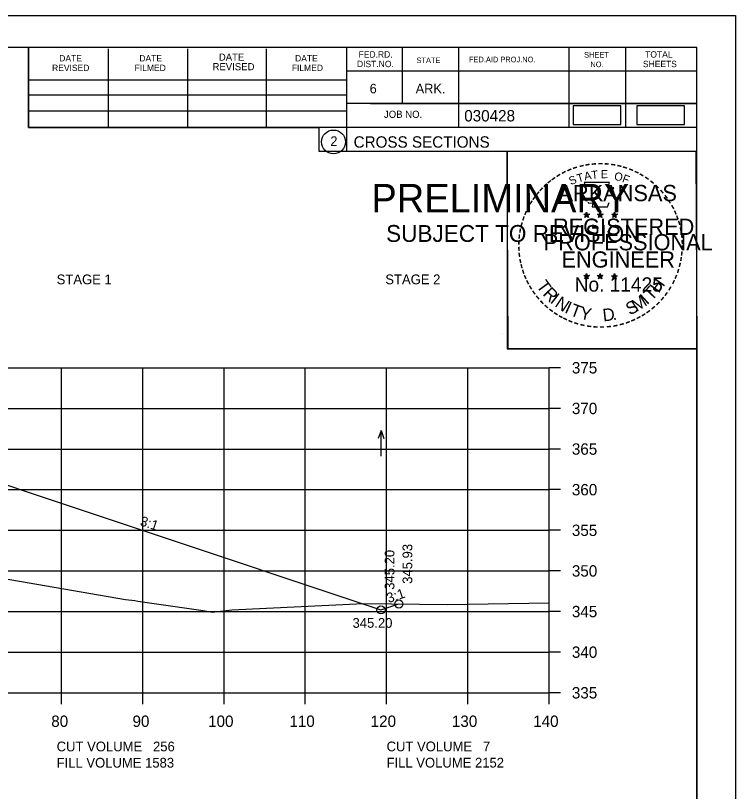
# Model space of a CAD drawing. Extents: x 1374859 to 1376773, y 382242 to 389804.
# Drawn here: x 1376684.8 to 1376773.4, y 383426.3 to 383521.8 of the extents above; entities that cross this region are included whole.
import ezdxf

# ---------------------------------------------------------------- set-up
doc = ezdxf.new("R2010")
doc.units = 0
for name, color, linetype in [('R_Axis', 7, 'Continuous'), ('R_Axis Annot', 7, 'Continuous'), ('R_Border', 7, 'Continuous'), ('R_Border PE', 7, 'Continuous'), ('R_Border Prem', 7, 'Continuous'), ('R_Exist Surface', 7, 'Continuous'), ('R_Fin Surface', 7, 'Continuous'), ('R_Grid', 7, 'Continuous'), ('R_MOT', 7, 'Continuous'), ('R_No Plot', 7, 'Continuous'), ('R_Water Annot', 7, 'Continuous'), ('R_Xsect Elev', 7, 'Continuous'), ('R_Xsect Slope', 7, 'Continuous')]:
    doc.layers.add(name, color=color, linetype=linetype)

msp = doc.modelspace()

# ---------------------------------------------------------------- linework, layer by layer
at = {"layer": 'R_Axis'}
for p, q in [((1376750.452, 383438.41), (1376750.452, 383478.41)), ((1376751.852, 383478.41), (1376750.452, 383478.41)), ((1376751.852, 383473.41), (1376750.452, 383473.41)), ((1376751.852, 383468.41), (1376750.452, 383468.41)), ((1376751.852, 383463.41), (1376750.452, 383463.41)), ((1376751.852, 383458.41), (1376750.452, 383458.41)), ((1376751.852, 383453.41), (1376750.452, 383453.41)), ((1376751.852, 383448.41), (1376750.452, 383448.41)), ((1376751.852, 383443.41), (1376750.452, 383443.41)), ((1376470.452, 383438.41), (1376750.452, 383438.41)), ((1376690.452, 383437.01), (1376690.452, 383438.41)), ((1376700.452, 383437.01), (1376700.452, 383438.41)), ((1376710.452, 383437.01), (1376710.452, 383438.41)), ((1376720.452, 383437.01), (1376720.452, 383438.41)), ((1376730.452, 383437.01), (1376730.452, 383438.41)), ((1376740.452, 383437.01), (1376740.452, 383438.41)), ((1376750.452, 383437.01), (1376750.452, 383438.41)), ((1376751.852, 383438.41), (1376750.452, 383438.41))]:
    msp.add_line(p, q, dxfattribs=at)
at = {"layer": 'R_Border'}
for p, q in [((1376452.452, 383517.87), (1376768.632, 383517.87)), ((1376686.372, 383507.99), (1376686.372, 383517.87)), ((1376696.232, 383507.99), (1376696.232, 383517.67)), ((1376705.992, 383507.99), (1376705.992, 383517.67)), ((1376715.672, 383507.99), (1376715.672, 383517.67)), ((1376725.532, 383517.87), (1376725.532, 383505.07)), ((1376732.372, 383517.87), (1376732.372, 383510.93)), ((1376739.312, 383517.87), (1376739.312, 383507.99)), ((1376752.892, 383517.87), (1376752.892, 383507.99)), ((1376759.832, 383517.87), (1376759.832, 383507.99)), ((1376768.632, 383312.41), (1376768.632, 383517.87)), ((1376768.632, 383514.93), (1376725.532, 383514.93)), ((1376768.632, 383514.95), (1376768.632, 383514.95)), ((1376686.372, 383513.85), (1376725.532, 383513.85)), ((1376686.372, 383511.99), (1376725.532, 383511.99)), ((1376768.632, 383510.93), (1376725.532, 383510.93)), ((1376728.492, 383510.93), (1376768.632, 383510.93)), ((1376686.372, 383507.99), (1376686.372, 383510.05)), ((1376686.372, 383510.05), (1376725.532, 383510.05)), ((1376768.632, 383507.99), (1376686.372, 383507.99)), ((1376725.532, 383505.07), (1376768.632, 383505.07))]:
    msp.add_line(p, q, dxfattribs=at)
msp.add_circle((1376723.918, 383506.206), 1.467, dxfattribs=at)
at = {"layer": 'R_Border PE'}
for p, q in [((1376754.717, 383497.325), (1376755.066, 383497.214)), ((1376754.717, 383497.325), (1376754.97, 383497.28)), ((1376754.717, 383497.325), (1376754.954, 383497.203)), ((1376754.85, 383496.917), (1376755.066, 383497.214)), ((1376755.066, 383497.579), (1376755.025, 383497.327)), ((1376755.066, 383497.214), (1376755.066, 383497.579)), ((1376755.066, 383497.579), (1376755.115, 383497.329)), ((1376755.413, 383497.325), (1376755.066, 383497.214)), ((1376755.279, 383496.917), (1376755.066, 383497.214)), ((1376755.413, 383497.325), (1376755.127, 383497.276)), ((1376755.279, 383496.917), (1376755.142, 383497.208)), ((1376755.413, 383497.325), (1376755.209, 383497.223)), ((1376756.387, 383497.325), (1376756.736, 383497.214)), ((1376756.387, 383497.325), (1376756.64, 383497.28)), ((1376756.387, 383497.325), (1376756.624, 383497.203)), ((1376756.52, 383496.917), (1376756.736, 383497.214)), ((1376756.736, 383497.579), (1376756.695, 383497.327)), ((1376756.736, 383497.214), (1376756.736, 383497.579)), ((1376756.736, 383497.579), (1376756.785, 383497.329)), ((1376757.083, 383497.325), (1376756.736, 383497.214)), ((1376756.949, 383496.917), (1376756.736, 383497.214)), ((1376757.083, 383497.325), (1376756.797, 383497.276)), ((1376756.949, 383496.917), (1376756.812, 383497.208)), ((1376757.083, 383497.325), (1376756.879, 383497.223)), ((1376758.151, 383497.313), (1376758.5, 383497.202)), ((1376758.151, 383497.313), (1376758.404, 383497.268)), ((1376758.151, 383497.313), (1376758.388, 383497.191)), ((1376758.5, 383497.567), (1376758.459, 383497.315)), ((1376758.5, 383497.202), (1376758.5, 383497.567)), ((1376758.5, 383497.567), (1376758.549, 383497.317)), ((1376758.847, 383497.313), (1376758.5, 383497.202)), ((1376758.847, 383497.313), (1376758.561, 383497.264)), ((1376758.847, 383497.313), (1376758.643, 383497.211)), ((1376754.85, 383496.917), (1376754.976, 383497.161)), ((1376754.85, 383496.917), (1376755.064, 383497.134)), ((1376755.279, 383496.917), (1376755.064, 383497.131)), ((1376756.52, 383496.917), (1376756.646, 383497.161)), ((1376756.52, 383496.917), (1376756.734, 383497.134)), ((1376756.949, 383496.917), (1376756.734, 383497.131)), ((1376758.284, 383496.905), (1376758.5, 383497.202)), ((1376758.284, 383496.905), (1376758.41, 383497.149)), ((1376758.284, 383496.905), (1376758.498, 383497.122)), ((1376758.713, 383496.905), (1376758.498, 383497.119)), ((1376758.713, 383496.905), (1376758.5, 383497.202)), ((1376758.713, 383496.905), (1376758.576, 383497.196)), ((1376754.713, 383489.752), (1376755.062, 383489.641)), ((1376754.713, 383489.752), (1376754.966, 383489.707)), ((1376754.713, 383489.752), (1376754.95, 383489.63)), ((1376754.846, 383489.344), (1376755.062, 383489.641)), ((1376754.846, 383489.344), (1376754.972, 383489.588)), ((1376755.062, 383490.006), (1376755.021, 383489.754)), ((1376755.062, 383489.641), (1376755.062, 383490.006)), ((1376755.062, 383490.006), (1376755.111, 383489.756)), ((1376755.409, 383489.752), (1376755.062, 383489.641)), ((1376755.275, 383489.344), (1376755.062, 383489.641)), ((1376755.409, 383489.752), (1376755.123, 383489.703)), ((1376755.275, 383489.344), (1376755.138, 383489.635)), ((1376755.409, 383489.752), (1376755.205, 383489.65)), ((1376756.382, 383489.752), (1376756.731, 383489.641)), ((1376756.382, 383489.752), (1376756.635, 383489.707)), ((1376756.382, 383489.752), (1376756.619, 383489.63)), ((1376756.515, 383489.344), (1376756.731, 383489.641)), ((1376756.515, 383489.344), (1376756.641, 383489.588)), ((1376756.731, 383490.006), (1376756.69, 383489.754)), ((1376756.731, 383489.641), (1376756.731, 383490.006)), ((1376756.731, 383490.006), (1376756.78, 383489.756)), ((1376757.078, 383489.752), (1376756.731, 383489.641)), ((1376756.944, 383489.344), (1376756.731, 383489.641)), ((1376757.078, 383489.752), (1376756.792, 383489.703)), ((1376756.944, 383489.344), (1376756.807, 383489.635)), ((1376757.078, 383489.752), (1376756.874, 383489.65)), ((1376758.149, 383489.742), (1376758.498, 383489.631)), ((1376758.149, 383489.742), (1376758.402, 383489.697)), ((1376758.149, 383489.742), (1376758.386, 383489.62)), ((1376758.282, 383489.334), (1376758.498, 383489.631)), ((1376758.282, 383489.334), (1376758.408, 383489.578)), ((1376758.498, 383489.996), (1376758.457, 383489.744)), ((1376758.498, 383489.631), (1376758.498, 383489.996)), ((1376758.498, 383489.996), (1376758.547, 383489.746)), ((1376758.845, 383489.742), (1376758.498, 383489.631)), ((1376758.711, 383489.334), (1376758.498, 383489.631)), ((1376758.845, 383489.742), (1376758.559, 383489.693)), ((1376758.711, 383489.334), (1376758.574, 383489.625)), ((1376758.845, 383489.742), (1376758.641, 383489.64)), ((1376754.846, 383489.344), (1376755.06, 383489.561)), ((1376755.275, 383489.344), (1376755.06, 383489.558)), ((1376756.515, 383489.344), (1376756.729, 383489.561)), ((1376756.944, 383489.344), (1376756.729, 383489.558)), ((1376758.282, 383489.334), (1376758.496, 383489.551)), ((1376758.711, 383489.334), (1376758.496, 383489.548))]:
    msp.add_line(p, q, dxfattribs=at)
for points in [[(1376754.758, 383501.203), (1376755.027, 383500.376)], [(1376758.269, 383500.281), (1376758.411, 383500.565), (1376757.726, 383500.541), (1376757.874, 383501.203), (1376754.758, 383501.203)], [(1376755.25, 383498.78), (1376755.25, 383498.693), (1376755.813, 383498.674), (1376755.759, 383498.201), (1376757.629, 383498.201), (1376757.83, 383498.737)], [(1376755.066, 383497.579), (1376755.279, 383496.917), (1376754.717, 383497.325), (1376755.413, 383497.325), (1376754.85, 383496.917), (1376755.066, 383497.579)], [(1376756.736, 383497.579), (1376756.949, 383496.917), (1376756.387, 383497.325), (1376757.083, 383497.325), (1376756.52, 383496.917), (1376756.736, 383497.579)], [(1376758.5, 383497.567), (1376758.713, 383496.905), (1376758.151, 383497.313), (1376758.847, 383497.313), (1376758.284, 383496.905), (1376758.5, 383497.567)], [(1376755.062, 383490.006), (1376755.275, 383489.344), (1376754.713, 383489.752), (1376755.409, 383489.752), (1376754.846, 383489.344), (1376755.062, 383490.006)], [(1376756.731, 383490.006), (1376756.944, 383489.344), (1376756.382, 383489.752), (1376757.078, 383489.752), (1376756.515, 383489.344), (1376756.731, 383490.006)], [(1376758.498, 383489.996), (1376758.711, 383489.334), (1376758.149, 383489.742), (1376758.845, 383489.742), (1376758.282, 383489.334), (1376758.498, 383489.996)]]:
    msp.add_lwpolyline(points, dxfattribs=at)
for centre, radius in [((1376755.065, 383497.213), 0.172), ((1376755.065, 383497.213), 0.145), ((1376755.065, 383497.213), 0.116), ((1376755.065, 383497.213), 0.0991), ((1376755.065, 383497.213), 0.0747), ((1376755.065, 383497.213), 0.0495), ((1376755.065, 383497.213), 0.0296), ((1376756.735, 383497.213), 0.172), ((1376756.735, 383497.213), 0.145), ((1376756.735, 383497.213), 0.116), ((1376756.735, 383497.213), 0.0991), ((1376756.735, 383497.213), 0.0747), ((1376756.735, 383497.213), 0.0495), ((1376756.735, 383497.213), 0.0296), ((1376758.499, 383497.201), 0.172), ((1376758.499, 383497.201), 0.145), ((1376758.499, 383497.201), 0.116), ((1376758.499, 383497.201), 0.0991), ((1376758.499, 383497.201), 0.0747), ((1376758.499, 383497.201), 0.0495), ((1376758.499, 383497.201), 0.0296), ((1376755.061, 383489.64), 0.172), ((1376755.061, 383489.64), 0.145), ((1376755.061, 383489.64), 0.116), ((1376755.061, 383489.64), 0.0991), ((1376755.061, 383489.64), 0.0747), ((1376755.061, 383489.64), 0.0495), ((1376755.061, 383489.64), 0.0296), ((1376756.73, 383489.64), 0.172), ((1376756.73, 383489.64), 0.145), ((1376756.73, 383489.64), 0.116), ((1376756.73, 383489.64), 0.0991), ((1376756.73, 383489.64), 0.0747), ((1376756.73, 383489.64), 0.0495), ((1376756.73, 383489.64), 0.0296), ((1376758.497, 383489.63), 0.172), ((1376758.497, 383489.63), 0.145), ((1376758.497, 383489.63), 0.116), ((1376758.497, 383489.63), 0.0991), ((1376758.497, 383489.63), 0.0747), ((1376758.497, 383489.63), 0.0495), ((1376758.497, 383489.63), 0.0296)]:
    msp.add_circle(centre, radius, dxfattribs=at)
at = {"layer": 'R_Exist Surface'}
msp.add_lwpolyline([(1376668.854, 383456.298), (1376674.332, 383454.055), (1376698.323, 383449.876), (1376699.464, 383449.757), (1376699.852, 383449.673), (1376707.879, 383448.53), (1376708.984, 383448.348), (1376711.42, 383448.606), (1376727.625, 383449.38), (1376737.959, 383449.29), (1376750.452, 383449.464)], dxfattribs=at)
at = {"layer": 'R_Fin Surface'}
msp.add_lwpolyline([(1376485.181, 383452.493), (1376502.811, 383446.616), (1376550.967, 383462.668), (1376558.854, 383463.983), (1376571.044, 383466.015), (1376580.967, 383466.65), (1376610.467, 383468.539), (1376639.967, 383470.428), (1376653.467, 383471.292), (1376669.721, 383468.583), (1376669.967, 383468.542), (1376729.762, 383448.61), (1376731.96, 383449.343)], dxfattribs=at)
at = {"layer": 'R_Grid'}
for p, q in [((1376470.452, 383478.41), (1376750.452, 383478.41)), ((1376470.452, 383478.41), (1376750.452, 383478.41)), ((1376690.452, 383438.41), (1376690.452, 383478.41)), ((1376690.452, 383438.41), (1376690.452, 383478.41)), ((1376700.452, 383438.41), (1376700.452, 383478.41)), ((1376700.452, 383438.41), (1376700.452, 383478.41)), ((1376710.452, 383438.41), (1376710.452, 383478.41)), ((1376710.452, 383438.41), (1376710.452, 383478.41)), ((1376720.452, 383438.41), (1376720.452, 383478.41)), ((1376720.452, 383438.41), (1376720.452, 383478.41)), ((1376730.452, 383438.41), (1376730.452, 383478.41)), ((1376730.452, 383438.41), (1376730.452, 383478.41)), ((1376740.452, 383438.41), (1376740.452, 383478.41)), ((1376740.452, 383438.41), (1376740.452, 383478.41)), ((1376750.452, 383438.41), (1376750.452, 383478.41)), ((1376750.452, 383438.41), (1376750.452, 383478.41)), ((1376470.452, 383473.41), (1376750.452, 383473.41)), ((1376470.452, 383473.41), (1376750.452, 383473.41)), ((1376470.452, 383468.41), (1376750.452, 383468.41)), ((1376470.452, 383468.41), (1376750.452, 383468.41)), ((1376470.452, 383463.41), (1376750.452, 383463.41)), ((1376470.452, 383463.41), (1376750.452, 383463.41)), ((1376470.452, 383458.41), (1376750.452, 383458.41)), ((1376470.452, 383458.41), (1376750.452, 383458.41)), ((1376470.452, 383453.41), (1376750.452, 383453.41)), ((1376470.452, 383453.41), (1376750.452, 383453.41)), ((1376470.452, 383448.41), (1376750.452, 383448.41)), ((1376470.452, 383448.41), (1376750.452, 383448.41)), ((1376470.452, 383443.41), (1376750.452, 383443.41)), ((1376470.452, 383443.41), (1376750.452, 383443.41)), ((1376470.452, 383438.41), (1376750.452, 383438.41)), ((1376470.452, 383438.41), (1376750.452, 383438.41))]:
    msp.add_line(p, q, dxfattribs=at)
at = {"layer": 'R_MOT'}
for points in [[(1376753.43, 383508.334), (1376759.263, 383508.334), (1376759.263, 383510.644), (1376753.43, 383510.644)], [(1376761.261, 383508.334), (1376767.094, 383508.334), (1376767.094, 383510.644), (1376761.261, 383510.644)]]:
    msp.add_lwpolyline(points, close=True, dxfattribs=at)
at = {"layer": 'R_No Plot'}
for p, q in [((1376440.051, 383521.765), (1376773.384, 383521.765)), ((1376744.666, 383482.615), (1376744.666, 383482.615))]:
    msp.add_line(p, q, dxfattribs=at)
for points in [[(1376440.044, 383521.765), (1376773.384, 383521.765), (1376773.384, 383308.427), (1376440.044, 383308.427)], [(1376686.372, 383517.87), (1376686.372, 383507.99), (1376722.104, 383507.99), (1376722.104, 383505.07), (1376745.303, 383505.07), (1376745.303, 383480.737), (1376768.632, 383480.737), (1376768.632, 383312.41), (1376452.452, 383312.41), (1376452.452, 383517.87)], [(1376745.303, 383505.07), (1376768.511, 383505.07), (1376768.632, 383480.737), (1376745.424, 383480.737)]]:
    msp.add_lwpolyline(points, close=True, dxfattribs=at)
for centre in [(1376731.96, 383449.343), (1376729.762, 383448.61)]:
    msp.add_circle(centre, 0.5, dxfattribs=at)
at = {"layer": 'R_Water Annot'}
for p, q in [((1376729.773, 383470.681), (1376729.423, 383469.72)), ((1376729.773, 383467.539), (1376729.773, 383470.681)), ((1376729.773, 383470.681), (1376730.123, 383469.72))]:
    msp.add_line(p, q, dxfattribs=at)

# ---------------------------------------------------------------- texts
at = {"layer": 'R_Axis Annot'}
for s, p in [('STAGE 1', (1376689.855, 383488.69)), ('STAGE 2', (1376730.296, 383488.692))]:
    msp.add_text(s, height=1.2, rotation=360, dxfattribs=at).set_placement(p)
for s, height, p in [('375', 1.4, (1376753.252, 383477.71)), ('370', 1.4, (1376753.252, 383472.71)), ('365', 1.4, (1376753.252, 383467.71)), ('360', 1.4, (1376753.252, 383462.71)), ('355', 1.4, (1376753.252, 383457.71)), ('350', 1.4, (1376753.252, 383452.71)), ('345', 1.4, (1376753.252, 383447.71)), ('340', 1.4, (1376753.252, 383442.71)), ('335', 1.4, (1376753.252, 383437.71)), ('80', 1.4, (1376689.19, 383434.21)), ('90', 1.4, (1376699.19, 383434.21)), ('100', 1.4, (1376708.49, 383434.21)), ('110', 1.4, (1376718.49, 383434.21)), ('120', 1.4, (1376728.49, 383434.21)), ('130', 1.4, (1376738.49, 383434.21)), ('140', 1.4, (1376748.49, 383434.21)), ('CUT VOLUME   256', 1.2, (1376689.855, 383431.203)), ('CUT VOLUME   7', 1.2, (1376730.452, 383431.21)), ('FILL VOLUME 1583', 1.2, (1376689.855, 383429.203)), ('FILL VOLUME 2152', 1.2, (1376730.452, 383429.21))]:
    msp.add_text(s, height=height, dxfattribs=at).set_placement(p)
at = {"layer": 'R_Border'}
for s, height, p in [('FED.RD.', 0.7819, (1376727.012, 383516.59)), ('SHEET', 0.684, (1376754.752, 383516.59)), ('TOTAL', 0.7819, (1376762.272, 383516.59)), ('DATE', 0.7819, (1376690.172, 383516.11)), ('DATE', 0.7819, (1376700.032, 383516.11)), ('DATE', 0.8792, (1376709.812, 383516.21)), ('DATE', 0.7819, (1376719.192, 383516.11)), ('STATE', 0.684, (1376734.132, 383515.91)), ('FED.AID PROJ.NO.', 0.684, (1376740.592, 383516.01)), ('REVISED', 0.7819, (1376689.292, 383514.93)), ('FILMED', 0.7819, (1376699.452, 383514.93)), ('REVISED', 0.8792, (1376709.032, 383515.03)), ('FILMED', 0.7819, (1376718.792, 383514.93)), ('DIST.NO.', 0.7819, (1376726.812, 383515.41)), ('NO.', 0.684, (1376755.532, 383515.41)), ('SHEETS', 0.7819, (1376761.992, 383515.41)), ('6', 1.172, (1376728.372, 383512.19)), ('ARK.', 1.1723, (1376734.032, 383512.19)), ('JOB NO.', 0.8792, (1376730.132, 383509.17)), ('030428', 1.4, (1376740.008, 383508.73)), ('2', 1.172, (1376723.536, 383505.719)), ('CROSS SECTIONS', 1.4, (1376726.395, 383505.5))]:
    msp.add_text(s, height=height, rotation=360, dxfattribs=at).set_placement(p)
at = {"layer": 'R_Border PE'}
for s, height, rotation, p in [('-', 1.6, 24.30721, (1376752.871, 383502.061)), ('-', 1.6, 19.17608, (1376753.505, 383502.33)), ('-', 1.6, 13.63015, (1376754.255, 383502.571)), ('-', 1.6, 10.21935, (1376754.933, 383502.733)), ('-', 1.6, 5.89682, (1376755.662, 383502.843)), ('-', 1.6, 0.18623, (1376756.434, 383502.915)), ('-', 1.6, 357.74304, (1376757.157, 383502.902)), ('-', 1.6, 352.16172, (1376757.901, 383502.846)), ('-', 1.6, 347.20489, (1376758.62, 383502.732)), ('-', 1.6, 342.3362, (1376759.255, 383502.577)), ('-', 1.6, 337.85509, (1376759.99, 383502.354)), ('-', 1.6, 34.06357, (1376751.641, 383501.374)), ('-', 1.6, 28.79182, (1376752.238, 383501.744)), ('S', 1, 21.59401, (1376753.112, 383500.881)), ('T', 1, 16.4036, (1376754.026, 383501.212)), ('A', 1, 11.21318, (1376754.852, 383501.463)), ('T', 1, 6.02276, (1376755.701, 383501.629)), ('E', 1, 0.83234, (1376756.806, 383501.739)), ('O', 1, 350.4515, (1376758.41, 383501.529)), ('F', 1, 340.07066, (1376759.364, 383501.301)), ('-', 1.6, 334.12109, (1376760.621, 383502.083)), ('-', 1.6, 329.64089, (1376761.2, 383501.8)), ('-', 1.6, 42.96224, (1376750.154, 383500.184)), ('-', 1.6, 38.95066, (1376750.587, 383500.601)), ('-', 1.6, 36.23174, (1376751.063, 383500.979)), ('-', 1.6, 325.86266, (1376761.843, 383501.439)), ('-', 1.6, 320.52971, (1376762.453, 383501.013)), ('-', 1.6, 50.61417, (1376749.303, 383499.22)), ('-', 1.6, 48.42305, (1376749.706, 383499.706)), ('ARKANSAS', 2, 360, (1376751.61, 383498.915)), ('-', 1.6, 315.57859, (1376763.052, 383500.525)), ('-', 1.6, 309.87973, (1376763.621, 383499.975)), ('-', 1.6, 54.23247, (1376748.89, 383498.653)), ('-', 1.6, 306.65218, (1376764.146, 383499.373)), ('-', 1.6, 62.87135, (1376748.252, 383497.512)), ('-', 1.6, 58.07063, (1376748.565, 383498.126)), ('-', 1.4, 303.67529, (1376764.632, 383498.805)), ('-', 1.6, 299.66835, (1376764.951, 383498.198)), ('-', 1.6, 67.77427, (1376747.993, 383496.901)), ('DWB', 0.01, 360, (1376755.053, 383497.209)), ('DWB', 0.01, 360, (1376756.723, 383497.209)), ('DWB', 0.01, 360, (1376758.487, 383497.198)), ('-', 1.6, 294.66279, (1376765.275, 383497.586)), ('-', 1.6, 75.46096, (1376747.577, 383495.557)), ('-', 1.6, 72.39447, (1376747.774, 383496.271)), ('REGISTERED', 2, 360, (1376750.932, 383494.766)), ('-', 1.6, 290.57283, (1376765.532, 383497.009)), ('-', 1.6, 285.12326, (1376765.766, 383496.429)), ('-', 1.6, 81.20126, (1376747.445, 383494.844)), ('-', 1.6, 280.54934, (1376765.966, 383495.687)), ('-', 1.6, 85.18634, (1376747.369, 383494.153)), ('PROFESSIONAL', 2, 360, (1376749.784, 383492.862)), ('-', 1.6, 276.59616, (1376766.128, 383494.919)), ('-', 1.6, 89.06224, (1376747.344, 383493.452)), ('-', 1.6, 274.33011, (1376766.188, 383494.197)), ('-', 1.6, 269.94067, (1376766.222, 383493.565)), ('-', 1.6, 94.19588, (1376747.379, 383492.727)), ('-', 1.6, 98.94793, (1376747.451, 383492.06)), ('ENGINEER', 2, 360, (1376751.971, 383490.737)), ('-', 1.6, 263.5172, (1376766.203, 383492.899)), ('-', 1.6, 101.71495, (1376747.586, 383491.327)), ('-', 1.6, 260.99529, (1376766.132, 383492.245)), ('-', 1.6, 105.45785, (1376747.748, 383490.732)), ('-', 1.6, 252.86809, (1376765.841, 383490.847)), ('-', 1.6, 255.7626, (1376766.022, 383491.567)), ('-', 1.6, 109.08742, (1376747.963, 383490.101)), ('-', 1.6, 114.06432, (1376748.217, 383489.505)), ('No. 11425', 1.757, 360, (1376753.599, 383487.786)), ('DWB', 0.01, 360, (1376755.049, 383489.636)), ('DWB', 0.01, 360, (1376756.718, 383489.636)), ('DWB', 0.01, 360, (1376758.485, 383489.626)), ('-', 1.6, 247.88866, (1376765.618, 383490.174)), ('-', 1.6, 115.72885, (1376748.522, 383488.887)), ('T', 1.54, 306.04056, (1376748.821, 383488.479)), ('H', 1.54, 54.60883, (1376763.941, 383487.514)), ('-', 1.6, 244.61971, (1376765.356, 383489.545)), ('-', 1.6, 120.44712, (1376748.879, 383488.301)), ('-', 1.6, 125.89344, (1376749.282, 383487.74)), ('R', 1.54, 314.00497, (1376749.584, 383487.432)), ('T', 1.54, 46.64442, (1376763.052, 383486.572)), ('-', 1.6, 233.84524, (1376764.56, 383488.14)), ('-', 1.6, 239.07125, (1376764.962, 383488.793)), ('-', 1.6, 130.71812, (1376749.744, 383487.188)), ('-', 1.6, 134.22381, (1376750.261, 383486.643)), ('I', 1.54, 321.96938, (1376750.484, 383486.5)), ('N', 1.54, 326.50021, (1376751.051, 383486.028)), ('M', 1.54, 32.65632, (1376761.206, 383485.247)), ('I', 1.54, 42.11359, (1376762.49, 383486.094)), ('-', 1.6, 231.25377, (1376764.13, 383487.574)), ('-', 1.6, 138.93382, (1376750.786, 383486.179)), ('I', 1.54, 335.36034, (1376752.259, 383485.242)), ('T', 1.54, 339.89117, (1376752.92, 383484.915)), ('Y', 1.54, 347.85558, (1376754.137, 383484.469)), ('D', 1.54, 6.39691, (1376757.122, 383484.111)), ('S', 1.54, 26.9312, (1376760.367, 383484.841)), ('-', 1.6, 221.08509, (1376763.129, 383486.501)), ('-', 1.6, 225.76533, (1376763.651, 383487.01)), ('-', 1.6, 144.64634, (1376751.342, 383485.773)), ('-', 1.6, 148.08978, (1376751.903, 383485.402)), ('-', 1.6, 151.57039, (1376752.482, 383485.077)), ('-', 1.6, 212.24909, (1376762.046, 383485.642)), ('-', 1.6, 215.73633, (1376762.58, 383486.029)), ('-', 1.6, 154.60019, (1376753.004, 383484.83)), ('-', 1.6, 158.56121, (1376753.628, 383484.576)), ('-', 1.6, 162.79826, (1376754.315, 383484.363)), ('.', 1.54, 13.76417, (1376758.314, 383484.238)), ('-', 1.6, 195.47429, (1376759.568, 383484.462)), ('-', 1.6, 200.71842, (1376760.245, 383484.704)), ('-', 1.6, 204.25161, (1376760.864, 383484.977)), ('-', 1.6, 207.35684, (1376761.488, 383485.296)), ('-', 1.6, 167.55551, (1376755.03, 383484.199)), ('-', 1.6, 173.11546, (1376755.802, 383484.089)), ('-', 1.6, 176.51827, (1376756.55, 383484.036)), ('-', 1.6, 181.59176, (1376757.294, 383484.055)), ('-', 1.6, 185.81666, (1376758.103, 383484.131)), ('-', 1.6, 191.28576, (1376758.839, 383484.263))]:
    msp.add_text(s, height=height, rotation=rotation, dxfattribs=at).set_placement(p)
at = {"layer": 'R_Border Prem'}
for s, height, p in [('PRELIMINARY', 3.5, (1376728.583, 383497.533)), ('DWB', 0.01, (1376729.329, 383499.382)), ('SUBJECT TO REVISION', 2.07511, (1376730.392, 383493.904))]:
    msp.add_text(s, height=height, rotation=360, dxfattribs=at).set_placement(p)
at = {"layer": 'R_Xsect Elev'}
for s, p in [('345.93', (1376733.616, 383451.823)), ('345.20', (1376731.418, 383451.091))]:
    msp.add_text(s, height=1.2, rotation=90, dxfattribs=at).set_placement(p)
msp.add_text('345.20', height=1.2, dxfattribs=at).set_placement((1376726.262, 383446.41))
at = {"layer": 'R_Xsect Slope'}
for rotation, p in [(341.56505, (1376700.023, 383459.05)), (18.43495, (1376730.703, 383449.451))]:
    msp.add_text('3:1', height=1.2, rotation=rotation, dxfattribs=at).set_placement(p)

doc.saveas('drawing.dxf')
